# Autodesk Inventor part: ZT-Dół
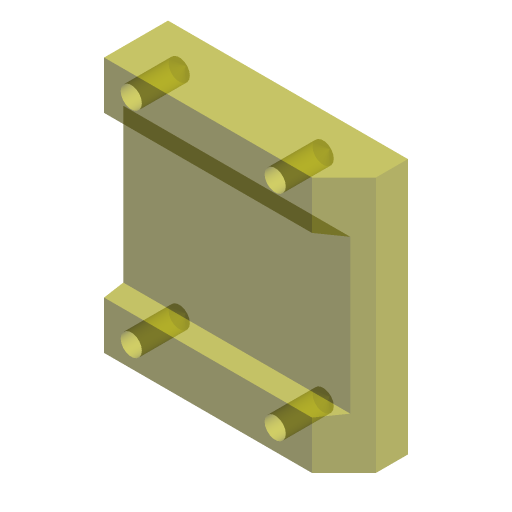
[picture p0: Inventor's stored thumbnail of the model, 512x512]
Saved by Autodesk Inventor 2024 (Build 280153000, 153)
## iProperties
Company: ATC
Shininess: 0.0
Length Units: 11269
Angle Units: 11279
Time Units: 11290
Mass Units: 11283
Length Display Precision: 3
Angle Display Precision: 2
Compacted: True
Created: 2023-03
Part Number: ZT-Dół
Document SubType Name: Modeling
Designer: Andrzej Jaskulski
Material: Kurs-AJ
Density: 1 g/cm^3
Appearance: Przezroczyste — żółte
Checked By: A.J.
Engr Approved By: Andrzej Jaskulski
Mfg Approved By: Andrzej Jaskulski
Authority: A.J.
Density: 0.0
Volumn: 0.0
Area: 0.0
PropertySet Name: Model Information
Control State: 0
Master: False
Checked Out: False
Title: A.J.: Kurs R2024-MEP
Author: Andrzej Jaskulski
Revision Number: 1/24
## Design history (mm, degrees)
node "Extrusion1" dims "d0" = 0, "d1" = 20
  sketch "Sketch2"
    geometry: L1 (75, 0)-(75, 80); L2 (75, 80)-(0, 80) reference; L3 (0, 80)-(0, 0) reference; L4 (0, 0)-(75, 0)
    constraints: 8 end point, 2 parallel, 1 perpendicular, 1 other
    dimensions: "d3" = 80 distance of L1.start L1.end (= ROZSTAW); "d2" = 75 distance of L1.end L2.end
node "Chamfer1" dims "d4" = 10, "d5" = 10, "d29" = 45 deg
node "Extrusion2" dims "d6" = 0, "d7" = 10
  sketch "Sketch3"
    geometry: L1 (0, -20)-(80, -20) reference; L2 (80, 0)-(0, 0) reference; L3 (15, -20)-(16.058, -14); L4 (16.058, -14)-(63.942, -14); L5 (63.942, -14)-(65, -20); L6 (40, -14)-(40, -20)
    constraints: 8 end point, 2 midpoint, 2 point on line, 1 equal length, 1 parallel, 1 vertical
    dimensions: "d9" = 6 distance between parallel lines of L1 L4; "d8" = 100 deg angle of L4 L3; "d10" = 15 distance of L3.start L1.start; "d23" = 15 distance of L5.end L1.end
node "Hole1" dims "d17" = 118 deg, "d18" = 60 deg, "d19" = 2, "d20" = 4, "d21" = 15, "d22" = 6.64, "d28" = 6
  sketch "Sketch4"
    geometry: L1 (53.5, 73.5)-(8.5, 73.5); L2 (8.5, 73.5)-(8.5, 6.5); L3 (8.5, 6.5)-(53.5, 6.5); L4 (53.5, 6.5)-(53.5, 73.5); L5 (0, 65)-(0, 80) reference; L6 (0, 80)-(65, 80) reference
    constraints: 8 end point, 2 parallel, 1 horizontal, 1 perpendicular
    dimensions: "d16" = 45 distance of L1.start L1.end; "d30" = 6.5 distance from line of L1.end L6; "d31" = 8.5 distance from line of L5 L1.end; "d32" = 67 distance of L1.end L2.end
node "Bryła1"
node "Korpusy bryłowe"
node "Korpusy powierzchniowe"
other parameters: "d25" = 45, "d27" = 8.5, "odstęp" = 6.5 [user parameter], "ROZSTAW" = 80 [user parameter; used in 1 equation term], "odstęp2" = 8.5 [user parameter]
